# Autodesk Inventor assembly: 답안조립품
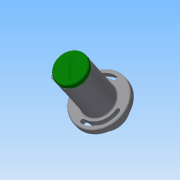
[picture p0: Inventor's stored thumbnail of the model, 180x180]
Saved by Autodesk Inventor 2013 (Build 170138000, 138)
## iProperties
Created: 2017-05
Part Number: 답안조립품
Document SubType Name: Assembly
Designer: Administrator
Author: Administrator
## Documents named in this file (19)
- C:\Users\Administrator\Desktop\470507V1021\답안조립품.iam
- C:\Users\Administrator\Desktop\470507V1021\V-벨트풀리.ipt
- C:\Users\Administrator\Desktop\470507V1021\너트 M10.ipt
- C:\Users\Administrator\Desktop\470507V1021\멈춤링 15 x 1.ipt
- C:\Users\Administrator\Desktop\470507V1021\멈춤링 35x1.6.ipt
- C:\Users\Administrator\Desktop\470507V1021\베어링 15 x 35 x 11.ipt
- C:\Users\Administrator\Desktop\470507V1021\본체.ipt
- C:\Users\Administrator\Desktop\470507V1021\부시1.ipt
- C:\Users\Administrator\Desktop\470507V1021\부시2.ipt
- C:\Users\Administrator\Desktop\470507V1021\사이드 커버.ipt
- 사이드 커버.ipt
- C:\Users\Administrator\Desktop\470507V1021\십자볼트 M3 x 10.ipt
- C:\Users\Administrator\Desktop\470507V1021\오일 실 15 25 7.ipt
- C:\Users\Administrator\Desktop\470507V1021\와셔 3x6.ipt
- C:\Users\Administrator\Desktop\470507V1021\와셔 4x16.ipt
- C:\Users\Administrator\Desktop\470507V1021\와셔 10x21.ipt
- C:\Users\Administrator\Desktop\470507V1021\축.ipt
- C:\Users\Administrator\Desktop\470507V1021\키 4 x 4 x 18.ipt
- C:\Users\Administrator\Desktop\470507V1021\탑 커버.ipt
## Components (1 placed, 1 different names)
1. V-벨트풀리:1 — 각도:2
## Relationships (1: Angle 1)
- 각도:2 [Angle]: V-벨트풀리:1
